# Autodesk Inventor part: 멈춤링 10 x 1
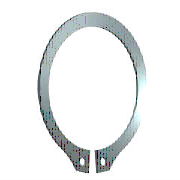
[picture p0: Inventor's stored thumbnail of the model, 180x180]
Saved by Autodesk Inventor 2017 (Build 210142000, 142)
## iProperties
IsCustomPart: 0
Created: 2021-07
Part Number: 멈춤링 10 x 1
Material: 강철, 연강
Description: 리테이닝 링(C형)
Document SubType Name: Modeling
Standard: KS B 1336
Designer: mdu
Standards Organization: KS
Language: ko-KR
Size Designation: 10 x 1
Categories: <MemberInstance><Categories><Category DisplayName="샤프트 부품" InternalName="7f7aeb1f-a693-4053-b835-cee3144e0d98" Mnemonic="SHFT"><Category DisplayName="써클립" Inter
Density: 7.86 g/cm^3
Mass: 0.423087 g
Surface Area: 1.9243 cm^2
Volume: 0.0538279 cm^3
Appearance: 파란색 - 벽 페인트 - 광택
Author: mdu
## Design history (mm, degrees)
sketch "스케치1"
  geometry: L1 (-6, 0)-(6, 0) reference; L2 (0, 20.189)-(0, -80.536) reference; L3 (-48.09, 0)-(48.09, 0) reference; L4 (-0.3, -9.791)-(-0.3, -12.791); L5 (-0.3, -6.54)-(-0.3, -13.29); L6 (-2.795, 1.6)-(3.672, 1.6); L7 (0.3, -6.54)-(0.3, -13.29); L8 (0.3, -9.791)-(0.3, -12.791); C1 r 0.6 at (-1.2, -11.486); C2 r 0.6 at (1.2, -11.486); A1 r 4.8 centre (0, -5) between (0.3, -9.791) and (-0.3, -9.791); A2 r 6.2 centre (0, -4.6) between (2.988, -10.033) and (-2.988, -10.033); A3 r 7.796 centre (0, -5) between (-1.418, -12.666) and (-0.3, -12.791); A4 r 1.2 centre (-1.2, -11.486) between (-2.383, -11.285) and (-1.418, -12.666); A5 r 1.2 centre (-3.566, -11.084) between (-2.383, -11.285) and (-2.988, -10.033); A6 r 1.2 centre (3.566, -11.084) between (2.988, -10.033) and (2.383, -11.285); A7 r 1.2 centre (1.2, -11.486) between (1.418, -12.666) and (2.383, -11.285); A8 r 7.796 centre (0, -5) between (0.3, -12.791) and (1.418, -12.666)
  constraints: 16 point on circle, 12 end point, 10 centre point, 9 symmetric about line, 5 point on line, 4 tangent, 3 coincident, 2 horizontal, 1 perpendicular, 1 vertical, 5 other
  dimensions: "d0" = 9.6 diameter of A1 (= ND); "d1" = 3 distance of L4.end L4.start (= SRB2); "d6" = 0.3 distance between parallel lines of L2 L5 (= 0.25 x SD5); "d7" = 1.6 distance between parallel lines of L6 L3 (= SRB1); "d8" = 0.4 distance of A1.centre A2.centre (= 0.25 x SRB1); "d9" = 1.2 radius of A4 (= SD5); "d10" = 1.2 radius of A5 (= SD5); "d11" = 0.9 distance from line of L4 A4.centre (= 0.75 x SD5); "d12" = 1.2 diameter of C1 (= SD5); "d13" = 1.2 diameter of C2 (= SD5); "d14" = 5 distance from line of A1.centre L1 (= 0.5 x WD)
extrude "본체" new body sketch "스케치1" distance "d2" = 1 (= SD); taper "d3" = 0 deg
workaxis "Work Axis1"
workplane "Work Plane1"
body "Solid1"
other parameters: "SD" = 1 [user parameter; used in 1 equation term], "SRB1" = 1.6 [user parameter; used in 2 equation terms], "ND" = 9.6 [user parameter; used in 1 equation term], "SRB2" = 3 [user parameter; used in 1 equation term], "SD5" = 1.2 [user parameter; used in 6 equation terms], "d15" = 0, "d16" = 0, "d17" = 0, "d41" = 0, "d42" = 0, "SD3" = 9.3 [user parameter], "WDMAX" = 11 [user parameter]
